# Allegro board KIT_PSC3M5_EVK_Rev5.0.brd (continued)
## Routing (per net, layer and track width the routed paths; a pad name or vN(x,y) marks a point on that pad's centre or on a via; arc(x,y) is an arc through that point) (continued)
VCC_FLASH: length 3.6
  TOP w0.508: U3.8 74.63,25.35 v1(74.55,25.27)
  BOTTOM w0.508: v1(74.55,25.27) 74.42,25.4 C66.2 73.19,25.4 73.17,25.42 R107.1
VCC_IN: length 24.8
  BOTTOM w0.381: TP9.1 107.28,23.65 ; TP9.1 106.2,22.57 ; TP9.1 105.12,23.65 ; 106.39,18.92 D4.K ; D4.K 106.39,21.46 ; D4.K 107.3,20.19 ; D4.K 105.47,20.19 ; U8.12 94.88,21.58 ; C82.1 98.17,22.65 ; C82.1 99.11,21.85 ; C82.1 97.23,21.85 ; C81.1 101.27,21.85 ; C81.1 99.39,21.85 ; C81.1 100.33,22.65 ; C84.1 96.27,21.68 ; C84.1 95.74,21.18 ; C84.1 96.79,21.18 ; 95.54,17.36 R124.1 94.87,16.94 ; 95.77,18.37 R121.2 96.27,17.78 ; C80.1 103.43,21.85 ; C80.1 101.55,21.85 ; C80.1 102.49,22.65 ; 106.39,14.86 D5.K ; D5.K 106.39,17.4 ; D5.K 107.3,16.13 ; D5.K 105.47,16.13 ; U8.13 94.93,21.35
VCC_IO_CAN: length 3.5
  TOP w0.292: U4.5 34.7,14.73
  TOP w0.381: v1(33.75,15.72) C40.2 34.44,14.99 34.7,14.73
  BOTTOM w0.381: R131.1 33.81,16.65 33.81,15.77 v1(33.75,15.72)
VCCD: length 2.3
  TOP w0.292: 69.34,41.15 69.27,41.08 U1.10
  TOP w0.381: 69.34,41.15 C11.1
VDD_POT: length 9.6
  BOTTOM w0.381: R49.2 113.86,55.6 ; R49.2 113.2,54.88 ; R49.2 113.2,56.32 ; 113.82,58.06 J9.2 ; J9.2 113.82,60 ; J9.2 112.85,59.03 ; J9.2 114.79,59.03 ; R1.3 126.6,63.74 ; R1.3 124.8,63.74 ; R1.3 125.7,64.64 ; R1.3 125.7,62.84
VDDA: length 19.9
  TOP w0.292: U1.66 59.14,33.05
  TOP w0.381: 59.14,33.05 59.14,32.02 C30.1 59.72,31.49 59.72,32.28 v1(59.84,32.41)
  L04_SIG2 w0.635: v1(54.76,28.22) v1(54.05,28.22)
  L05_PWR w0.381: 110.31,59.03 J9.1 ; J9.1 111.28,60 ; J9.1 111.28,58.06 ; J9.1 112.25,59.03
  BOTTOM w0.381: 111.28,58.06 J9.1 ; J9.1 111.28,60 ; J9.1 110.31,59.03 ; 111.7,54.88 R49.1 ; R49.1 111.03,55.6 ; R49.1 111.7,56.32 ; 54.51,28.71 R93.1 53.79,29.37
  BOTTOM w0.508: R80.1 60.11,32.68 v1(59.84,32.41) 59.33,31.9 C63.1 FB2.2
  vias: v1(42.57,41.68) v1(42.57,41.05) v1(42.57,40.41) v1(42.57,39.78) v1(42.57,39.14) v1(43.46,41.3) v1(43.46,40.54) v1(43.46,39.78)
VDDD: length 8.1
  TOP w0.292: 69.37,40.54 69.33,40.58 U1.9
  TOP w0.381: 69.37,40.54 69.75,40.16 70,40.16 70.79,39.37 C18.1 v1(70.89,40.16)
  BOTTOM w0.381: R44.1 42.55,56.64 v1(42.32,56.41) ; v1(32.41,26.82) 32.28,26.7 R109.1
  BOTTOM w0.508: v1(70.89,40.16) 71.07,39.98 C54.1 72.66,39.27 FB1.2
VDDIO_0: length 16.4
  TOP w0.292: v1(69.37,46.38) 69.06,46.08 U1.20 ; 53.49,42.08 U1.49 ; U1.40 56.64,48.88 56.35,49.17
  TOP w0.381: v1(54.89,50.08) 54.93,50.12 C2.1 55.68,49.43 55.93,49.17 56.35,49.17 ; v1(51.08,41.94) 51.28,42.14 C9.1 53.11,42.14 53.17,42.08 53.49,42.08
  BOTTOM w0.381: C51.1 50.28,41.53 50.69,41.94 v1(51.08,41.94) ; 70.13,46.16 C46.1 ; C46.1 70.66,46.66 ; C46.1 69.6,46.66 ; 54,49.41 C44.1 v1(54.89,50.08) ; 73.05,45.85 R55.1 ; 70.81,46.52 C45.1 71.53,45.85
  BOTTOM w0.508: R55.1 C45.1
VDDIO_1: length 7.5
  TOP w0.292: U1.80 66.14,33.76 67.31,32.59 68.2,32.59 C27.1 68.25,32.92 67.87,33.3 v1(67.84,33.3)
  BOTTOM w0.381: R78.1 C59.1 68.3,32.54 67.84,32.99 v1(67.84,33.3)
VIN: length 16.2
  TOP w0.381: 98.77,14.6 R42.1 ; R42.1 99.46,15.52 ; R42.1 98.77,16.44
  BOTTOM w0.381: D5.A 111.7,16.13 ; D5.A 110.78,14.86 ; D5.A 109.87,16.13 ; 112.52,15.67 R132.1 ; R132.1 113.02,16.09 ; R132.1 112.03,16.09 ; 116.04,5.88 J20.1 ; J20.1 116.04,8.85 ; J20.1 114.92,7.37 ; J20.1 117.16,7.37 ; 113.68,12.62 C92.1 ; C92.1 113.68,14.05 ; C92.1 113.01,13.34 ; D6.1 113.71,11.92 ; D6.1 113.09,11.3 ; D6.1 113.71,10.68
  vias: v1(99.09,14.38) v1(99.97,15.14) v1(99.97,14.38)
VIN_EXP: length 127.5
  TOP w0.381: 96.17,15.52 R42.2 ; R42.2 96.87,16.44 ; R42.2 96.87,14.6 ; 59.93,5.08 J24.2 ; J24.2 60.96,6.11 ; J24.2 60.96,4.05 ; J24.2 61.99,5.08 ; J1.1 86.87,11.87 ; J1.1 86.87,9.72 ; J1.1 85.79,10.79 ; J1.1 87.95,10.79
  L04_SIG2 w0.889: J24.2 58.93,7.11 32.56,7.11 28.85,10.82 28.85,54.89 31.8,57.84 40.84,57.84 51.23,68.22 60.05,68.22 J5.39
AN_A0: length 8.8
  TOP w0.178: U1.53 53.21,40.08 53.06,39.93 50.46,39.93 C14.2 50.28,40.52 v1(50.16,40.64)
  BOTTOM w0.178: R68.1 49.81,40.28 v1(50.16,40.64)
AN_A1: length 9.3
  TOP w0.178: v1(50.27,38.73) 50.28,38.72 C19.2 50.93,37.85 52.66,39.58 U1.54
  BOTTOM w0.178: R70.1 50.24,38.76 v1(50.27,38.73)
AN_A2: length 10.6
  TOP w0.178: v1(50.27,36.83) 50.28,36.82 C22.2 50.8,35.94 51.05,36.2 51.05,37.24 52.89,39.08 U1.55
  BOTTOM w0.178: v1(50.27,36.83) 49.86,37.24 R71.1
AN_A3: length 12.1
  TOP w0.178: v1(50.27,34.92) 50.28,34.91 C24.2 50.88,34.04 51.44,34.59 51.44,36.93 53.08,38.58 U1.56
  BOTTOM w0.178: v1(50.27,34.92) 47.79,34.92 R74.1
AN_A4: length 13.6
  TOP w0.178: v1(50.27,33.02) 50.28,33.01 C26.2 50.93,32.13 51.21,32.41 51.21,33.63 51.84,34.26 51.84,36.65 53.26,38.08 U1.57
  BOTTOM w0.178: R77.1 47.79,33.4 49.89,33.4 v1(50.27,33.02)
AN_A5: length 15.1
  TOP w0.178: v1(50.27,31.11) 50.28,31.1 C29.2 50.95,30.23 51.66,30.94 51.66,33.38 52.25,33.96 52.25,36.4 53.43,37.58 U1.58
  BOTTOM w0.178: v1(50.27,31.11) 48.72,32.66 R82.1
AN_A6: length 16.6
  TOP w0.178: U1.59 53.56,37.08 52.63,36.14 52.63,33.71 52.15,33.22 52.15,29.51 50.98,28.35 50.31,28.35 C38.2 50.28,29.2 v1(50.27,29.21)
  BOTTOM w0.178: v1(50.27,29.21) 48.34,31.14 R85.1
AN_A7: length 18.1
  TOP w0.178: U1.60 53.72,36.58 53.09,35.94 53.09,33.5 52.63,33.05 52.63,29.18 51.38,27.94 51.38,26.85 50.95,26.42 C39.2 50.28,27.29 v1(50.27,27.3)
  BOTTOM w0.178: v1(50.27,27.3) 47.96,29.62 R97.1
AN_B2: length 8.9
  TOP w0.178: U1.63 57.64,33.51 56.9,32.77 55.3,32.77 v1(55.07,32.54) 54.36,31.83 C31.2
  BOTTOM w0.178: R94.1 52.73,31.47 53.16,31.9 54.38,31.9 55.02,32.54 v1(55.07,32.54)
AN_B3: length 6.8
  TOP w0.178: U1.64 58.14,33.07 v1(57.68,32.61) 57.51,32.44 56.16,32.44 55.88,32.16 C32.2
  BOTTOM w0.178: v1(57.68,32.61) 57.81,32.49 R91.1
AN_B4: length 6.9
  TOP w0.178: U1.67 59.64,33.4 v1(60.68,32.36) 60.68,31.96 C33.2
  BOTTOM w0.178: R90.1 62.89,31.45 62.53,31.8 61.24,31.8 v1(60.68,32.36)
AN_B5: length 8
  TOP w0.178: C34.2 63.02,32.41 v1(62.76,32.66) 61.24,32.66 60.14,33.76 U1.68
  BOTTOM w0.178: v1(62.76,32.66) 63.01,32.66 R89.1
AN_B6: length 9.5
  TOP w0.178: U1.69 60.64,33.81 61.28,33.17 63.14,33.17 63.86,32.46 v1(64.47,32.46) 64.54,32.46 64.92,32.08 C35.2
  BOTTOM w0.178: R88.1 66.62,31.47 66.19,31.9 65.02,31.9 v1(64.47,32.46)
AN_B7: length 11.1
  TOP w0.178: U1.70 61.14,33.78 61.37,33.55 63.27,33.55 63.88,32.94 65.71,32.94 v1(65.89,32.77) 65.96,32.77 66.7,32.03 C36.2
  BOTTOM w0.178: R87.1 68.25,31.39 66.88,32.77 v1(65.89,32.77)
ARD_A0: length 74.8
  TOP w0.178: J24.23 87.66,3.78 87.66,6.38 88.8,7.52 90.2,7.52 91.95,9.27 J2.1
  L03_SIG1 w0.157: v1(45.63,41.3) 46.65,40.28 49.56,40.28 56.34,33.5 64.08,33.5 65.38,32.21 66.9,32.21 68.22,30.89 69.62,30.89 71.48,29.03 74.02,29.03 77.34,25.7 82.14,25.7 87.15,20.7 87.83,20.7 91.21,17.32 91.21,11.53 J2.1
  BOTTOM w0.178: v1(45.63,41.3) 45.63,40.41 R68.2
ARD_A1: length 78
  TOP w0.178: J2.2 94.49,9.19 92.74,7.44 92.74,4.09 91.44,2.79 J24.25
  L03_SIG1 w0.157: J2.2 93.22,9.53 91.62,9.53 90.83,10.31 90.83,16.15 88.57,18.41 88.57,19.15 87.5,20.22 86.92,20.22 81.81,25.32 76.25,25.32 73.89,27.69 72.16,27.69 69.34,30.51 68.02,30.51 66.65,31.88 64.39,31.88 63.12,33.15 56.67,33.15 55.58,32.05 53.16,32.05 50.88,34.34 48.56,34.34 47.02,35.89 47.02,36.35 v1(44.6,38.76)
  BOTTOM w0.178: R70.2 v1(44.6,38.76)
ARD_A2: length 79.8
  TOP w0.178: J2.3 97.03,9.4 95.28,7.65 95.28,3.84 J24.27
  L03_SIG1 w0.157: v1(44.6,37.24) 46.15,35.69 46.15,35.36 49.78,31.72 55.8,31.72 56.54,32.46 57.05,32.46 57.96,31.55 66.42,31.55 67.92,30.05 69.19,30.05 72.01,27.23 73.86,27.23 76.76,24.33 82.12,24.33 86.74,19.71 87.43,19.71 88.11,19.02 88.11,18.08 90.45,15.75 90.45,10.06 91.34,9.17 95.4,9.17 J2.3
  BOTTOM w0.178: R71.2 v1(44.6,37.24)
ARD_A3: length 92.1
  TOP w0.178: J24.22 86.36,6.35 88.42,8.41 89.69,8.41 90.53,9.25 90.53,11.66 91.26,12.4 97.51,12.4 99.11,10.79 J2.4
  L03_SIG1 w0.157: v1(44.6,35.71) 47.07,33.25 47.07,32.03 47.9,31.19 48.62,31.19 49.2,30.61 50.57,30.61 51.36,31.39 55.85,31.39 56.03,31.22 66.22,31.22 67.79,29.64 68.96,29.64 71.78,26.82 73.79,26.82 76.61,24 81.91,24 86.64,19.28 87.05,19.28 87.63,18.69 87.63,18.01 90.07,15.57 90.07,9.8 91.16,8.71 96.09,8.71 96.88,9.5 98.27,9.5 J2.4
  BOTTOM w0.178: R74.2 v1(44.6,35.71)
ARD_A4: length 208.5
  L03_SIG1 w0.157: 46.05,32.36 46.15,32.26 ; 46.05,32.36 15.98,32.36 J16.1 ; 46.05,32.36 46.15,32.46 ; 46.15,32.26 46.15,31.88 47.29,30.73 48.26,30.73 48.74,30.25 50.85,30.25 51.66,31.06 55.68,31.06 55.85,30.89 65.94,30.89 67.59,29.24 68.81,29.24 74.37,23.67 81.71,23.67 86.39,19 86.39,17.81 89.69,14.5 89.69,9.55 90.86,8.38 99.69,8.38 J2.5 ; 46.15,32.26 46.15,32.46 ; 46.15,32.46 46.15,32.72 v1(44.65,34.21) 41.91,36.96 41.91,46.28 38.25,49.94 12.73,49.94 9.55,53.11 9.55,55.3 9.19,55.65 7.01,55.65 J8.2
  L03_SIG1 w0.178: J16.1 6.99,6.35 J21.2
  L04_SIG2 w0.157: J2.5 102.11,9.53 99.85,7.26 90.45,7.26 88.9,5.71 J24.24
  BOTTOM w0.157: R77.2 44.68,34.19 v1(44.65,34.21)
ARD_A5: length 215
  L03_SIG1 w0.157: 8.26,54.36 8.26,53.14 12.09,49.3 38.25,49.3 41.45,46.1 41.45,36.55 44.5,33.5 v1(44.5,32.84) 14.17,32.84 5.74,24.41 5.74,17.4 4.47,16.13 4.47,4.47 5.11,3.84 7.01,3.84 8.26,5.08 ; v1(44.89,28.68) 45.08,28.88 48.92,28.88 49.07,28.73 51.1,28.73 51.92,29.54 57.66,29.54 57.96,29.84 61.37,29.84 61.62,29.59 66.04,29.59 67.16,28.47 68.22,28.47 73.94,22.76 76.86,22.76 82.83,16.79 86.13,16.79 88.93,14 88.93,9.04 90.4,7.57 102.57,7.57 104.65,9.65 J2.6
  L04_SIG2 w0.157: J2.6 100.74,6.88 93.37,6.88 91.57,5.08 J24.26
  BOTTOM w0.157: R82.2 44.68,32.66 v1(44.5,32.84) 44.09,32.44 44.09,29.44 44.85,28.68 v1(44.89,28.68)
ARD_A6: length 89.5
  L03_SIG1 w0.157: v1(44.6,31.14) 46.02,29.72 51.56,29.72 51.71,29.87 57.53,29.87 57.86,30.2 61.57,30.2 61.85,29.92 66.34,29.92 67.4,28.85 68.43,28.85 73.94,23.34 81.43,23.34 83.69,21.08 83.69,17.93 84.35,17.27 86.16,17.27 89.31,14.12 89.31,9.3 90.63,7.98 101.45,7.98 103.4,9.93 103.4,11.58 104.04,12.22 105.77,12.22 J2.7 103.15,6.76 103.15,6.63 J24.34
  BOTTOM w0.178: R85.2 v1(44.6,31.14)
ARD_A7: length 58.1
  L03_SIG1 w0.157: v1(44.58,29.62) 44.58,29.46 44.42,29.31 44.42,28.49 45.05,27.86 48.56,27.86 49.05,28.35 51.28,28.35 52.15,29.21 57.78,29.21 58.06,29.49 61.19,29.49 61.42,29.26 63.27,29.26 63.93,28.6 63.93,27.58 64.69,26.82 67.06,26.82 72.59,21.29 76.12,21.29 81.58,15.82 81.58,14.88 82.98,13.49 82.98,8.64 83.82,7.8 J24.20
  BOTTOM w0.178: R97.2 v1(44.58,29.62)
ARD_B0: length 24.4
  TOP w0.178: R36.1 40.67,35.97 v1(43.48,38.79) ; v1(53.24,32.66) 54,33.43 56.08,33.43 56.64,33.99 U1.61
  L03_SIG1 w0.157: v1(43.48,38.79) 44.09,39.4 45.62,39.4 48.84,36.17 50.57,36.17 53.24,33.5 v1(53.24,32.66)
ARD_B0_EXP: length 70.3
  TOP w0.178: R33.1 v1(39.14,37.47)
  BOTTOM w0.178: v1(39.14,37.47) 39.14,25.3 38.25,24.41 38.25,11.81 40.49,9.58 53.85,9.58 56.87,6.55 77.27,6.55 J24.16
ARD_B1: length 33.7
  TOP w0.178: v1(38.51,51.21) 38.49,51.22 R7.2 ; v1(54,32.66) 54.43,33.1 56.59,33.1 57.14,33.65 U1.62
  L03_SIG1 w0.157: v1(38.51,51.21) 42.67,47.04 42.67,43.23 46.89,39.01 49.25,39.01 54,34.26 v1(54,32.66)
ARD_B1_EXP: length 88.3
  TOP w0.178: v1(40.41,52.73) 39.99,53.15 R7.1
  BOTTOM w0.178: v1(40.41,52.73) 40.23,52.55 40.23,39.78 39.65,39.19 39.65,25.04 38.68,24.08 38.68,12.09 40.74,10.03 54.1,10.03 57.12,7.01 79.35,7.01 J24.18
ARD_B2: length 47.7
  L03_SIG1 w0.157: v1(52.88,28.12) 53.87,27.13 59.97,27.13 61.32,25.78 66.98,25.78 67.72,25.04 67.72,24.13 72.26,19.58 75.87,19.58 78.05,17.4 78.05,9.12 80.04,7.14 80.04,3.78 J24.17
  BOTTOM w0.178: v1(52.88,28.12) 52.73,28.27 R94.2
ARD_B3: length 44.3
  L03_SIG1 w0.157: v1(57.56,28.35) 58.37,27.53 63.27,27.53 64.54,26.26 67.01,26.26 72.36,20.9 76.02,20.9 80.16,16.76 80.16,12.73 80.54,12.34 80.54,8.79 82.58,6.76 82.58,3.78 J24.19
  BOTTOM w0.178: v1(57.56,28.35) 57.56,29.12 R91.2
ARD_B5: length 41.5
  L03_SIG1 w0.157: v1(64.8,28.09) 65.33,27.56 67.06,27.56 72.97,21.64 76.4,21.64 85.62,12.42 85.62,9.8 89.05,6.38 92.68,6.38 J24.28
  BOTTOM w0.178: R89.2 v1(64.8,28.09)
ARD_B6: length 42.6
  L03_SIG1 w0.157: J24.30 94.84,6.76 89.81,6.76 88.16,8.41 88.16,11.58 87.4,12.34 86.21,12.34 76.53,22.02 73.28,22.02 67.21,28.09 v1(66.62,28.09)
  BOTTOM w0.178: R88.2 v1(66.62,28.09)
ARD_B7: length 56.7
  TOP w0.178: J24.32 101.6,7.62 106.55,7.62 J2.8
  L03_SIG1 w0.157: v1(68.25,27.71) 73.56,22.4 76.68,22.4 86.23,12.85 87.53,12.85 88.54,11.84 88.54,8.79 90.22,7.11 97.03,7.11 J24.32
  BOTTOM w0.178: R87.2 v1(68.25,27.71)
CAN_RX1: length 49.6
  TOP w0.178: v1(41.92,16.41) 41.92,23.64 45.36,27.08 45.36,40.03 44.65,40.74 44.65,46.08 45.54,46.96 v1(46.41,46.96) ; v1(57.43,46.25) 58.14,46.97 U1.37
  L03_SIG1 w0.157: v1(46.41,46.96) 50.06,46.96 51.51,48.41 54.25,48.41 55.4,47.27 57.18,47.27 57.43,47.02 v1(57.43,46.25)
  BOTTOM w0.178: R137.2 v1(41.92,16.41)
CAN_STB: length 1.6
  TOP w0.178: U4.8 v1(35.46,12.1)
  BOTTOM w0.178: v1(35.46,12.1) 35.46,12.09 R151.2
CAN_TX1: length 49.7
  TOP w0.178: v1(42.06,13.36) 42.7,14 42.7,23.14 45.87,26.31 45.87,40.28 45.14,41.02 45.14,44.63 v1(46.89,46.38) ; U1.38 57.64,47.1 57.3,46.76 v1(56.92,46.76)
  L03_SIG1 w0.157: v1(56.92,46.76) 55.4,46.76 54.13,48.03 51.89,48.03 50.24,46.38 v1(46.89,46.38)
  BOTTOM w0.178: v1(42.06,13.36) 41.92,13.22 R148.1
CS: length 35.2
  TOP w0.15: v1(85.42,27.23) 85.4,27.2 85.4,26.43 R41.2
  TOP w0.178: v1(62,36.86) 61.64,36.5 U1.71
  L03_SIG1 w0.157: v1(85.42,27.23) 84.56,26.37 77.67,26.37 73.91,30.12 72.01,30.12 67.82,34.32 61.7,34.32 61.04,34.98 61.04,36.55 61.34,36.86 v1(62,36.86)
  BOTTOM w0.15: R20.2 85.4,27.2 v1(85.42,27.23)
DFU_SW1: length 94.1
  TOP w0.178: v1(70.26,8.41) 71.12,7.54 J24.10 ; v1(66.83,46.79) 66.55,46.79 66.14,47.19 U1.21
  L04_SIG2 w0.157: v1(66.83,46.79) 67.31,46.79 68.86,45.24 68.86,39.4 69.42,38.84 70.43,38.84 71.67,37.61 71.67,36.59 76.5,31.75 87.78,31.75 88.7,30.84 88.7,26.24 85.39,22.94 83.24,22.94 76.1,15.8 76.1,14.55 72.92,11.38 72.92,6.88 J24.10
  BOTTOM w0.178: v1(70.26,8.41) 58.06,8.41 54.51,11.96 52.91,11.96 J19.2
DFU_SW2: length 71.6
  TOP w0.178: U1.22 65.64,46.34 65.3,46 65.3,42.7 v1(65.05,42.44)
  L03_SIG1 w0.178: J22.2 52.15,2.95 58.57,2.95 59.46,3.84 69.82,3.84 J24.9
  L04_SIG2 w0.157: J24.9 69.93,3.73 69.93,6.7 67.84,8.79 67.84,12.09 68.86,13.11 68.86,15.52 69.57,16.23 69.57,24.54 68.78,25.32 68.78,33.12 67.34,34.57 67.34,37.24 65.05,39.52 v1(65.05,42.44)
ECO_IN: length 5.7
  TOP w0.178: U1.14 69.11,43.08 70.38,44.35 72.11,44.35 72.42,44.65 72.42,45.35 R18.2
ECO_OUT: length 7.1
  TOP w0.178: U1.15 68.98,43.58 69.37,43.97 69.37,45.49 70.13,46.25 72.24,46.25 72.42,46.43 R13.2
ETM_TRACE_CLK: length 51.3
  TOP w0.15: J14.12 105.03,44.96 104.3,45.69 v1(99.7,45.69)
  TOP w0.157: v1(64.24,52.3) 64.26,52.32 71.27,52.32 72.16,51.44 79.38,51.44 80.11,50.7 v1(90.07,50.7)
  L03_SIG1 w0.157: v1(90.07,50.7) 91.9,50.7 92.06,50.54 92.06,49.92 92.21,49.76 92.53,49.76 92.69,49.92 92.69,50.54 92.84,50.7 94.68,50.7 v1(99.7,45.69)
  BOTTOM w0.157: R24.1 61.33,52.06 61.9,52.63 63.91,52.63 v1(64.24,52.3)
ETM_TRACE_D0: length 51.6
  TOP w0.15: J14.14 99.19,46.23 97.51,44.55 97.51,38.29 96.88,37.65 96.88,34.49 95.83,33.45 95.83,30.68 97.3,29.22 97.3,27.75 97,27.46 90.19,27.46 90.04,27.31 90.04,25.22 89.89,25.07 89.59,25.07 89.44,25.22 89.44,27.31 89.29,27.46 88.99,27.46 88.84,27.31 88.84,25.22 88.69,25.07 88.39,25.07 88.24,25.22 88.24,27.31 88.09,27.46 87.73,27.46 87.58,27.31 87.58,25.04 87.35,24.81 v1(86.43,24.81)
  BOTTOM w0.15: R20.1 v1(86.43,24.81)
ETM_TRACE_D1: length 51.7
  TOP w0.15: J14.16 99.87,47.5 97.16,44.78 97.16,38.38 96.55,37.77 96.55,34.72 95.43,33.6 95.43,30.51 96.8,29.13 96.8,28.09 96.49,27.79 86.16,27.79 83.39,30.56 81,30.56 80.65,30.2 80.65,28.35 80.44,28.14 v1(79.07,28.14)
  BOTTOM w0.15: R16.1 78.26,28.12 78.29,28.14 v1(79.07,28.14)
ETM_TRACE_D2: length 51.8
  TOP w0.15: v1(86.36,28.32) 85.95,28.73 85.95,29.31 86.16,29.51 86.89,29.51 87.12,29.29 87.12,28.4 87.38,28.14 87.64,28.14 87.79,28.29 87.79,28.93 87.94,29.08 88.24,29.08 88.39,28.93 88.39,28.29 88.54,28.14 88.84,28.14 88.99,28.29 88.99,28.93 89.14,29.08 89.44,29.08 89.59,28.93 89.59,28.29 89.74,28.14 93.25,28.14 93.4,28.29 93.4,29.47 93.55,29.62 93.85,29.62 94,29.47 94,28.29 94.15,28.14 94.45,28.14 94.6,28.29 94.6,29.47 94.75,29.62 95.05,29.62 95.2,29.47 95.2,28.29 95.35,28.14 96.04,28.14 96.27,28.37 96.27,29.08 95.02,30.33 95.02,33.73 96.22,34.93 96.22,37.9 96.8,38.48 96.8,45.01 100.56,48.77 J14.18
  BOTTOM w0.15: v1(86.36,28.32) 86.36,28.27 86.21,28.12 R12.1
ETM_TRACE_D3: length 51.8
  TOP w0.15: J14.20 101.24,50.04 96.37,45.16 96.37,38.53 95.89,38.05 95.89,35.15 94.59,33.86 94.59,31.24 92.08,28.73 90.6,28.73 89.26,30.07 84.53,30.07 83.62,30.99 80.52,30.99 78.19,28.66 78.19,25.13 v1(78.51,24.81)
  BOTTOM w0.15: R10.1 v1(78.51,24.81)
EXT_CLK: length 6.3
  TOP w0.178: R27.2 75.12,39.04 76.99,37.17 TP4.1
HDR_3V3: length 39.6
  L03_SIG1 w0.381: 76.71,11.87 J1.5 75.63,10.79
  L04_SIG2 w0.381: J21.7 19.48,5.08 ; J21.7 18.41,6.15 ; J21.7 18.41,4.01 ; 22.23,22.29 J16.7 ; J16.7 23.3,23.37 ; J16.7 22.23,24.45
  L05_PWR w0.381: J1.5 76.71,11.87 ; J1.5 75.63,10.79 ; J1.5 76.71,9.72 ; J1.5 77.79,10.79 ; J24.39 109.22,3.57 ; J24.39 110.25,2.54 ; J24.39 109.22,1.51 ; J24.39 108.19,2.54 ; J8.7 19.48,54.36 ; J8.7 18.41,53.29 ; J8.7 17.35,54.36 ; J8.7 18.41,55.42 ; J5.2 109.22,65.8 ; J5.2 110.25,64.77 ; J5.2 108.19,64.77 ; J5.2 109.22,63.74 ; J21.7 18.41,6.15 ; J21.7 19.48,5.08 ; J21.7 18.41,4.01 ; J21.7 17.35,5.08
  BOTTOM w0.292: Q7.4 69.87,15.9 69.75,15.77 v1(69.75,15.27)
  BOTTOM w0.381: J1.5 76.71,11.87 ; J1.5 77.79,10.79 ; J1.5 75.63,10.79 ; J1.5 76.71,9.72 ; R141.2 76.48,13.79 ; R141.2 75.81,14.51 ; R141.2 75.81,13.07 ; 75.93,14.89 Q5.S ; Q5.S 75.93,16.13 ; Q5.S 76.6,15.51 ; 70.35,15.49 Q7.4
  vias: v1(70.13,14.76)
HDR_5V0: length 24.3
  TOP w0.381: J1.4 80.33,10.79 ; J1.4 79.25,11.87 ; J1.4 78.17,10.79 ; J1.4 79.25,9.72
  L03_SIG1 w0.381: 22.23,45.15 J12.7 ; J12.7 23.3,46.23 ; J12.7 21.15,46.23 ; J12.7 22.23,47.31 ; J21.1 3.17,6.15 ; J21.1 3.17,4.01 ; J21.1 2.11,5.08 ; J8.1 4.24,54.36 ; J8.1 3.17,53.29 ; J8.1 2.11,54.36 ; J8.1 3.17,55.42
  BOTTOM w0.292: v1(79.38,16.28) 79.4,16.28 79.5,16.38 Q6.4
  BOTTOM w0.381: 85.68,15.42 Q4.S 86.35,16.04 ; J1.4 79.25,11.87 ; J1.4 79.25,9.72 ; J1.4 80.33,10.79 ; 85.53,13.23 R143.2 ; R143.2 86.23,14.15 ; R143.2 85.53,15.07 ; 80.02,15.97 Q6.4
  vias: v1(73.69,8.92) v1(74.32,9.17) v1(74.32,8.53) v1(75.08,9.17) v1(75.08,8.53) v1(79.65,15.65) v1(86.64,14.76) v1(86.64,14.12) v1(86.64,13.49)
HDR_I2C_SCL: length 164.1
  TOP w0.178: J3.10 56.82,59.05 54.64,56.87 v1(54.64,56.29)
  L03_SIG1 w0.157: v1(87.16,52.1) 87.16,52.74 86.23,53.67 81.97,53.67 81.32,54.31 81.32,54.79 84.96,58.43 84.96,61.26 v1(84.48,61.75) ; v1(54.64,56.29) 53.95,55.6 41.93,55.6 41.5,56.03 28.68,56.03 28.17,56.54 15.52,56.54 J8.5
  L04_SIG2 w0.157: J12.5 17.14,49.12 13.34,52.93 J8.5 ; J5.21 82.65,68.48 80.42,68.48 79.89,67.95 79.89,64.01 77.88,62 62.89,62 J3.10
  L04_SIG2 w0.178: J5.21 84.99,66.14 84.99,62.26 v1(84.48,61.75)
  BOTTOM w0.178: R47.2 v1(87.16,52.1) ; J12.5 17.14,34.7 10.82,28.37 10.82,19.76 9.58,18.52 9.58,4.04 10.08,3.53 11.79,3.53 J21.5
HDR_I2C_SDA: length 162.5
  TOP w0.178: v1(55.56,56.32) 55.88,56.01 60.68,56.01 62.48,57.81 J3.9
  L03_SIG1 w0.157: v1(83.46,61.75) 84.35,60.86 84.35,58.45 80.98,55.07 80.98,54.18 81.9,53.25 84.2,53.25 v1(85.36,52.1) ; v1(55.56,56.32) 54.97,56.92 41.81,56.92 41.55,56.67 29.18,56.67 28.8,57.05 13.49,57.05 J8.4
  L04_SIG2 w0.157: J3.9 65.05,61.62 78.26,61.62 80.2,63.56 80.2,66.23 J5.23
  L04_SIG2 w0.178: J12.6 19.68,48.31 14.63,53.37 14.63,55.14 14,55.78 12.22,55.78 J8.4 ; v1(83.46,61.75) 82.58,62.64 82.58,66.19 81.46,67.31 J5.23
  BOTTOM w0.178: J21.4 12.09,6.38 12.09,18.54 13.36,19.81 13.36,28.93 19.68,35.26 J12.6 ; v1(85.36,52.1) R48.2
I2C_SCL: length 39.4
  TOP w0.178: U1.79 65.64,35.54 v1(66.19,36.09)
  BOTTOM w0.178: R53.2 88.81,48.41 88.87,48.47 R50.1 88.87,49.61 88.66,49.82 R47.1 88.66,51.78 87.43,53.01 84.76,53.01 81.46,49.71 81.46,46.38 78.82,43.74 74.7,43.74 72.77,41.81 69.24,41.81 68.12,40.69 68.12,39.22 66.19,37.29 v1(66.19,36.09)
I2C_SDA: length 29.5
  TOP w0.178: U1.2 v1(66.81,37.08)
  BOTTOM w0.178: v1(66.81,37.08) 68.73,39 68.73,40.41 69.57,41.25 73.03,41.25 74.96,43.18 79.07,43.18 82.02,46.13 82.02,49.42 83.04,50.44 R48.1 83.86,49.69 83.7,49.54 R51.1 83.7,48.47 83.76,48.41 R54.2
KP_I2C_SCL: length 7.8
  TOP w0.178: U2.38 v1(90.29,43.55)
  BOTTOM w0.178: v1(90.29,43.55) 90.29,45.78 89.18,46.89 87.58,46.89 87.4,47.07 87.4,47.59 R53.1
KP_I2C_SDA: length 9.4
  TOP w0.178: v1(89.81,42.95) 89.89,42.88 U2.39
  BOTTOM w0.178: R54.1 85.26,46.75 85.62,46.38 87.76,46.38 87.84,46.47 88.23,46.47 88.5,46.19 88.5,45.71 88.96,45.25 89.35,45.25 89.81,44.79 v1(89.81,42.95)
KP_RESET: length 29.7
  TOP w0.157: U2.3 v1(85.89,33.28)
  TOP w0.178: R25.2 v1(101.36,44.58)
  L03_SIG1 w0.157: v1(101.36,44.58) 101.36,36.94 100.25,35.84 99.7,35.84 98.63,36.91 95.91,36.91 95,35.99 95,33.86 93.61,32.47 92.24,32.47 91.03,33.68 86.28,33.68 v1(85.89,33.28)
KP_SWCLK: length 17.5
  TOP w0.157: U2.47 86.69,42.02 v1(86.69,43.26)
  TOP w0.178: v1(97.49,37.49) 97.61,37.36 R37.1
  L03_SIG1 w0.157: v1(86.69,43.26) 86.79,43.36 87.43,43.36 88.34,42.44 91.97,42.44 92.23,42.19 95.1,42.19 v1(95.12,42.21)
  BOTTOM w0.178: v1(97.49,37.49) 97.49,40.74 96.01,42.21 v1(95.12,42.21)
KP_SWDIO: length 17.7
  TOP w0.157: v1(87.2,42.8) 87.09,42.69 U2.46
  TOP w0.178: R39.1 98.46,36.31 v1(98.44,36.33)
  L03_SIG1 w0.157: v1(95.68,41.63) 95.66,41.61 92.02,41.61 91.74,41.88 88.11,41.88 v1(87.2,42.8)
  BOTTOM w0.178: v1(98.44,36.33) 97.92,36.86 97.23,36.86 96.93,37.16 96.93,40.39 v1(95.68,41.63)
KP_USB_DM: length 41.9
  TOP w0.114: J15.B7 123.43,29.1 123.57,29.23 123.92,29.23 v1(124.21,28.94) ; J15.A7 122,30.1 121.86,30.23 121.6,30.23 v1(121.31,29.94)
  L03_SIG1 w0.114: v1(97.34,36.12) 97.06,35.84 96.64,35.84 96.38,35.58 96.38,34.78 98.55,32.61 116.54,32.61 118.93,30.22 121.03,30.22 v1(121.31,29.94) 121.59,30.22 121.95,30.22 122.95,29.22 123.93,29.22 v1(124.21,28.94)
  BOTTOM w0.114: U7.1 119.33,30.37 119.9,30.37 120.85,29.41 121.7,29.41 121.95,29.66 121.95,30.12 121.83,30.23 121.6,30.23 v1(121.31,29.94) ; v1(97.34,36.12) 97.05,35.83 96.58,35.83 R72.1
KP_USB_DP: length 41.8
  TOP w0.114: v1(121.31,30.75) 121.6,30.46 121.87,30.46 122.01,30.6 J15.B6 ; v1(124.21,29.75) 123.92,29.46 123.57,29.46 123.43,29.6 J15.A6
  L03_SIG1 w0.114: v1(124.21,29.75) 123.93,29.47 123.06,29.47 122.06,30.47 121.59,30.47 v1(121.31,30.75) 121.03,30.47 119.03,30.47 116.64,32.86 98.66,32.86 96.63,34.88 96.63,35.47 96.75,35.59 97.06,35.59 v1(97.34,35.31)
  BOTTOM w0.114: R75.1 96.58,35.6 97.05,35.6 v1(97.34,35.31) ; v1(121.31,30.75) 121.6,30.46 121.93,30.46 122.17,30.21 122.17,29.57 121.79,29.18 120.76,29.18 119.81,30.14 119.33,30.14 U7.2
KP_VBUS: length 12.3
  BOTTOM w0.381: 112.57,20.06 R117.1 ; R117.1 113.07,20.48 ; R117.1 112.08,20.48 ; Q3.D 103.02,26.44 ; Q3.D 102.55,25.82 ; Q3.D 103.02,25.2 ; Q3.D 103.49,25.82 ; 105.95,27.2 R102.2 106.64,26.28 ; R108.2 100.56,26.06 ; R108.2 99.61,26.78 ; R108.2 99.61,25.03 ; D4.A 111.7,20.19 ; D4.A 110.78,18.92 ; D4.A 110.78,21.46 ; D4.A 109.87,20.19
KP_VBUS_IN: length 9.3
  TOP w0.381: TP7.1 v1(117.5,27.84)
  BOTTOM w0.381: R102.1 109.24,27.2 ; R102.1 108.54,28.12 ; R102.1 108.54,26.28 ; D3.K 120.1,27.08 ; D3.K 119.48,27.7 ; D3.K 118.86,27.08 ; C65.1 118.35,26.94 ; C65.1 116.91,26.94 ; C65.1 117.63,27.61 ; 109.12,30.25 Q2.D ; Q2.D 110.36,30.25 ; Q2.D 109.74,29.78
  vias: v1(121.06,32.28) v1(121.06,27.46) v1(121.44,27.97) v1(121.69,32.28)
LPCOMP0_INN: length 68.6
  L04_SIG2 w0.157: v1(79.88,29.54) 77.67,29.54 76.38,30.84 74.8,30.84 71.32,34.32 70.13,34.32 68.86,35.59 68.86,37.87 67.72,39.01 67.72,44.04 67.16,44.6 66.73,44.6 66.45,44.88 66.45,45.36 65.56,46.25 65.56,47.65 67.59,49.68 67.59,53.11 72.03,57.56 84.35,57.56 85.62,58.83 85.62,59.72 87.45,61.54 90.53,61.54 92.52,63.54 92.52,65.85 J5.13
  BOTTOM w0.15: R95.1 79.81,29.62 v1(79.88,29.54)
LPCOMP0_INP: length 77.7
  L04_SIG2 w0.157: v1(86.82,27.2) 86.16,26.54 77.19,26.54 75.44,28.3 74.12,28.3 67.72,34.7 67.72,37.36 65.68,39.4 65.68,42.57 64.41,43.84 64.41,48.41 66.32,50.32 66.32,59.79 67.77,61.24 84.73,61.24 87.53,64.03 87.53,66.14 J5.19
  BOTTOM w0.15: R113.1 86.9,27.1 86.82,27.18 v1(86.82,27.2)
LPCOMP1_INN: length 69.7
  L04_SIG2 w0.157: J5.17 88.9,66.85 89.98,65.77 89.98,63.57 89.6,63.19 87.44,63.19 85.12,60.86 69.88,60.86 68.86,59.84 68.86,57.81 66.7,55.65 66.7,50.06 64.8,48.16 64.8,44.09 66.07,42.82 66.07,39.52 68.1,37.49 68.1,35.05 74.35,28.8 75.67,28.8 76.73,27.74 78.51,27.74 v1(78.95,27.3)
  BOTTOM w0.15: R100.1 v1(78.95,27.3)
LPCOMP1_INP: length 76.4
  L04_SIG2 w0.157: J5.15 91.44,66.8 90.36,65.72 90.36,63.31 89.89,62.84 87.6,62.84 85.22,60.46 72.14,60.46 71.4,59.72 71.4,57.94 67.08,53.62 67.08,49.81 65.18,47.9 65.18,44.22 67.21,42.19 67.21,39.01 68.48,37.74 68.48,35.33 70,33.81 70.89,33.81 74.32,30.38 76.12,30.38 77.42,29.08 87.33,29.08 v1(87.86,29.62)
  BOTTOM w0.15: R104.1 v1(87.86,29.62)
MISO: length 34.2
  TOP w0.178: v1(63.02,36.86) 62.64,36.48 U1.73
  L03_SIG1 w0.157: v1(85.24,30.53) 85.24,30.05 84.76,29.57 82.02,29.57 80.09,31.5 73.96,31.5 72.14,33.32 72.14,35.2 71.76,35.59 69.86,35.59 69.7,35.74 69.7,36.49 69.55,36.65 69.23,36.65 69.07,36.49 69.07,35.74 68.92,35.59 68.6,35.59 68.44,35.74 68.44,36.49 68.29,36.65 67.97,36.65 67.81,36.49 67.81,35.74 67.66,35.59 66.04,35.59 64.41,37.21 63.37,37.21 v1(63.02,36.86)
  BOTTOM w0.15: R105.1 85.4,30.38 v1(85.24,30.53)
MOSI: length 34.2
  TOP w0.178: U1.72 v1(62.14,35.84)
  L03_SIG1 w0.157: v1(77.45,30.61) 77.93,31.09 79.24,31.09 79.4,30.93 79.4,29.34 79.3,29.24 78.91,29.24 78.75,29.39 78.75,29.87 78.6,30.02 78.28,30.02 78.12,29.87 78.12,29.43 78,29.31 77.48,29.31 75.77,31.01 73.94,31.01 73.62,31.33 73.4,31.33 72.97,30.91 72.75,30.91 72.53,31.13 72.53,31.35 72.95,31.78 72.95,32 72.73,32.22 72.51,32.22 72.08,31.8 71.86,31.8 71.64,32.02 71.64,32.24 72.06,32.67 72.06,32.89 71.65,33.3 71.4,33.3 71.24,33.46 71.24,34.51 71.09,34.67 70.77,34.67 70.61,34.51 70.61,33.46 70.46,33.3 69.95,33.3 69.26,33.99 69.26,34.22 69.66,34.62 69.66,34.84 69.43,35.06 69.21,35.06 68.81,34.66 68.59,34.66 68.12,35.13 64.59,35.13 63.47,36.25 62.55,36.25 v1(62.14,35.84)
  BOTTOM w0.15: R96.1 v1(77.45,30.61)
P0_1: length 54.9
  TOP w0.178: R21.2 70.26,43.46 v1(69.88,43.08)
  L04_SIG2 w0.157: v1(73.56,52.6) 74.9,53.95 97.26,53.95 100.85,57.54 100.85,61.4 102.9,63.45 102.9,66.07 J5.5
  BOTTOM w0.178: v1(69.88,43.08) 72.31,43.08 74.45,45.21 74.45,51.71 v1(73.56,52.6)
P1_0: length 72
  TOP w0.178: R17.2 v1(70,45.36)
  L04_SIG2 w0.157: v1(97.31,8.92) 91.59,8.92 88.16,12.34 88.16,23.34 90.91,26.09 90.91,31.88 88.32,34.47 80.9,34.47 v1(70,45.36)
  BOTTOM w0.178: J24.37 106.68,2.59 105.44,3.84 105.44,6.12 102.64,8.92 v1(97.31,8.92)
P1_1: length 44.4
  TOP w0.178: R13.1 70.92,48.26 v1(70.64,48.54)
  L04_SIG2 w0.157: v1(70.64,48.54) 70.64,51.98 73.68,55.02 80.42,55.02 81.08,55.68 93.65,55.68 95.66,57.68 95.66,59.33 100.23,63.91 100.23,65.94 J5.7
P2_0: length 42.8
  TOP w0.15: R158.2 99.94,42.41 v1(99.85,42.32) 99.96,42.2 R28.2 R29.2
  TOP w0.178: v1(66.95,45.08) U1.18
  L03_SIG1 w0.157: v1(99.85,42.32) 98.76,42.32 94.11,46.96 83.79,46.96 79.02,42.19 69.84,42.19 v1(66.95,45.08)
P2_1: length 45.2
  TOP w0.15: R31.2 R30.2 v1(99.96,40.4)
  TOP w0.178: U1.19 66.53,45.58 v1(65.94,44.98)
  L03_SIG1 w0.157: v1(65.94,44.98) 66.37,44.55 66.88,44.55 69.62,41.81 75.08,41.81 75.77,41.12 77.85,41.12 78.41,41.68 79.38,41.68 84.24,46.53 93.83,46.53 v1(99.96,40.4)
P3_0: length 45.5
  TOP w0.178: J4.8 85.12,57.3 82.07,57.3 81.56,57.81 81.56,61.49 81.28,61.77 J5.24 ; U1.23 65.14,49.9 v1(65.56,50.32)
  L03_SIG1 w0.157: v1(65.56,50.32) 68.88,50.32 76.48,57.91 76.48,59.71 79.02,62.26 85.5,62.26 86.87,60.88 J4.8
P3_1: length 144.9
  TOP w0.178: v1(65.56,51.33) 65.56,51.08 64.64,50.16 U1.24
  L03_SIG1 w0.157: v1(65.56,51.33) 65.18,51.33 64.41,50.57 63.45,50.57 63.14,50.88 62.46,50.88 58.57,54.76 v1(58.19,54.76) 55.65,57.3 30.48,57.3 30.1,57.68 20.09,57.68 13.34,64.44 J6.4
  L04_SIG2 w0.157: J18.4 13.34,17.7 10.82,20.22 10.82,30.25 20.98,40.41 20.98,49.05 17.17,52.86 17.17,56.29 13.34,60.12 J6.4 ; J5.28 74.32,62.89 61.24,62.89 58.19,59.84 v1(58.19,54.76)
P3_VDD: length 16.3
  L03_SIG1 w0.381: J17.1 118.65,21.95 ; J17.1 117.68,20.98 ; J17.1 117.68,22.91
  L03_SIG1 w1.016: 116.41,21.95 J17.1
  L04_SIG2 w0.381: 117.68,20.98 J17.1 ; J17.1 117.68,22.91 ; J17.1 118.65,21.95 ; J17.1 116.71,21.95
  BOTTOM w0.381: 73.77,48.02 R55.2 73.05,48.69 ; 61.7,29.37 FB2.1 60.99,28.71 ; 63.76,38.76 R69.2 64.43,38.04 ; v1(70.26,34.95) 70.37,34.84 R78.2 ; 73.39,37.76 FB1.1 72.67,37.09 ; 75.36,32.42 R157.2
  BOTTOM w0.635: R157.2 74.36,33.08 v1(74.3,33.15)
  vias: v1(61.11,28.45) v1(61.75,28.45) v1(63.91,37.74) v1(64.67,37.74) v1(72.92,49.05) v1(73.43,36.98) v1(73.56,49.05) v1(73.94,37.49) v1(74.42,32.51)
P4_4: length 22.6
  TOP w0.178: R23.2 v1(76.96,52.2) ; U1.31 61.14,45.85 v1(61.01,45.72)
  L03_SIG1 w0.157: v1(61.01,45.72) 61.26,45.97 61.26,47.17 62.26,48.16 62.43,48.16 62.43,48.16 68.76,48.16 70.43,49.83 74.6,49.83 v1(76.96,52.2)
P4_4_EXP: length 18
  TOP w0.178: R23.1 76.96,55.3 76.48,55.78 76.48,59.97 75.84,60.6 70.21,60.6 J5.36
P4_5: length 122.8
  TOP w0.178: J5.37 63.5,67.18 62.26,65.94 62.26,61.37 61.24,60.35 61.24,57.68 v1(60.48,56.92) ; v1(60.86,49.3) 60.64,49.08 U1.32
  L03_SIG1 w0.157: J8.8 22.2,53.11 39.27,53.11 40.16,54 48.34,54 51.79,50.55 57.99,50.55 59.69,48.84 60.4,48.84 v1(60.86,49.3)
  BOTTOM w0.178: J8.8 21.13,54.36 26.31,49.17 26.31,14.5 20.95,9.14 J21.8 ; v1(60.48,56.92) 59.05,56.92 56.92,54.79 56.92,50.98 58.09,49.81 60.35,49.81 v1(60.86,49.3)
P5_0: length 125
  TOP w0.178: U1.35 59.14,46.95 59.26,46.84 v1(59.26,46.28)
  L03_SIG1 w0.157: v1(59.26,46.28) 60.01,46.28 60.48,46.75 60.48,47.5 62.03,49.05 68.66,49.05 70.69,51.08 v1(71.65,51.08)
  L03_SIG1 w0.178: v1(59.26,46.28) 58.55,45.57 55.5,45.57 54.25,46.81 v1(53.19,46.81)
  L04_SIG2 w0.157: v1(71.65,51.08) 89.03,51.08 89.46,51.51 98.07,51.51 104.29,45.29 104.29,21.87 108.48,17.68 108.48,9.8 107.47,8.79 106.45,8.79 104.14,6.48 J24.36
  L04_SIG2 w0.178: v1(53.19,46.81) 51.68,48.32 51.68,52.44 52.6,53.37 52.6,57.53 52.52,57.62 52.52,62.17 54.83,64.48 v1(55.72,64.48)
  BOTTOM w0.178: R160.2 v1(55.72,64.48)
P5_2: length 67.5
  BOTTOM w0.178: J24.35 102.9,3.78 102.9,6.25 101.24,7.9 57.81,7.9 54.25,11.46 48.29,11.46 44.35,15.39 R136.2
P5_3: length 63.5
  BOTTOM w0.178: R148.2 44.35,12.34 45.92,10.77 54.18,10.77 57.38,7.57 98.65,7.57 100.36,5.87 100.36,3.78 J24.33
P5LP1_2: length 29.2
  TOP w0.178: v1(109.42,31.52) 109.54,31.4 SW3.1 SW3.2 ; U2.13 89.89,32.97 90.37,32.49 v1(90.37,30.28)
  L03_SIG1 w0.157: v1(109.42,31.52) 98.91,31.52 97.36,29.97 90.68,29.97 v1(90.37,30.28)
P5LP1_4: length 32.3
  TOP w0.157: U2.15 90.69,33.06 90.96,32.79 90.96,30.23 v1(91.69,29.49)
  L03_SIG1 w0.157: v1(115.63,25.97) 110.91,30.68 98.76,30.68 97.56,29.49 v1(91.69,29.49)
  BOTTOM w0.178: R106.2 v1(115.63,25.97)
P5LP_SIO_VREF: length 2.9
  TOP w0.191: v1(85.98,42.98) 86.29,42.67 U2.48
  BOTTOM w0.381: v1(85.98,42.98) R61.2 R62.2
P5LP_SWCLK: length 32.4
  TOP w0.157: U2.12 89.49,32.15 v1(89.81,31.83)
  TOP w0.178: v1(98.02,31.47) 105.26,31.47 112.8,39.01 112.8,39.65 J25.4
  L03_SIG1 w0.157: v1(98.02,31.47) 96.72,31.47 96.22,30.96 91.58,30.96 90.71,31.83 v1(89.81,31.83)
P5LP_SWDIO: length 32.9
  TOP w0.157: v1(88.54,31.65) 89.09,32.19 U2.11
  TOP w0.178: v1(97,30.71) 97.03,30.68 105.74,30.68 113.06,38 113.69,38 114.68,38.99
  L03_SIG1 w0.157: v1(88.54,31.65) 89.05,31.14 90.47,31.14 91.21,30.4 96.7,30.4 v1(97,30.71)
P5LP_VCCD: length 19.2
  TOP w0.191: U2.57 83.57,39.27 ; U2.26 93.34,38.07
  TOP w0.381: 83.57,39.27 83.54,39.24 C15.1 v1(82.14,39.95) ; 93.34,38.07 C17.1 v1(93.12,39.01)
  L03_SIG1 w0.635: v1(93.12,39.01) 92.48,39.65 92.48,40.03 91.26,41.25 83.44,41.25 v1(82.14,39.95)
P5LP_VDD: length 36.1
  TOP w0.191: U2.67 83.76,35.27 83.54,35.05 ; 83.58,41.44 83.75,41.27 U2.52 ; U2.35 91.49,42.88 ; U2.44 87.89,42.85 ; U2.59 83.63,38.47 83.54,38.38 ; U2.17 91.49,33.3 91.57,33.22 ; U2.24 93.16,37.27
  TOP w0.381: 91.57,33.22 91.87,32.92 C28.1 v1(91.87,31.45) ; 83.54,35.05 C23.1 v1(82.14,35.91) ; 87.89,42.85 87.76,42.98 C4.1 87.14,43.97 v1(86.77,44.35) ; 83.58,41.44 82.98,42.04 C8.1 v1(82.14,42.85) ; 93.16,37.27 93.35,37.47 C21.1 94.29,37.49 94.26,37.51 94.26,38.18 v1(94.39,38.3) ; 91.49,42.88 91.57,42.96 C6.1 92.35,43.97 v1(92.48,43.84) ; v1(82.14,37.16) C20.1 83.13,37.97 83.54,38.38
  L05_PWR w0.381: 114.68,48.18 J25.1 ; J25.1 113.71,49.15 ; J25.1 114.68,50.12 ; J25.1 115.65,49.15
  BOTTOM w0.381: R108.1 v1(98.11,25.08) ; R108.1 v1(97.21,26.06) ; R108.1 98.11,26.78 ; v1(92.48,43.84) 92.35,43.97 C6.1 ; C56.1 94.26,38.18 v1(94.39,38.3) ; v1(96.79,33.34) 96.32,33.81 R79.1 ; C23.1 v1(82.14,35.91) ; C20.1 v1(82.14,37.16) ; v1(86.77,44.35) 87.14,43.97 C4.1 ; C8.1 v1(82.14,42.85) ; C28.1 v1(91.87,31.45)
P5LP_XRES: length 33.6
  TOP w0.157: v1(88.42,33.17) 88.69,33.44 U2.10
  TOP w0.178: v1(97.16,32.23) 104.27,32.23 111.53,39.5 111.53,40.92 J25.3
  L03_SIG1 w0.157: v1(88.42,33.17) 90.83,33.17 91.97,32.03 93.95,32.03 94.16,32.23 v1(97.16,32.23)
P7_4: length 17.5
  TOP w0.15: U1.48 54.66,42.55 53.29,42.55 52.48,43.36 52.48,47.32 54.43,49.28 54.43,50.34 55.73,51.64 59.08,51.64 v1(59.8,52.36)
  BOTTOM w0.15: R159.2 59.83,52.34 v1(59.8,52.36)
P7_6: length 100.3
  TOP w0.178: J5.22 83.82,62.87 82.8,61.85 J3.1 ; U1.51 57.02,41.08 v1(57.05,41.05)
  L03_SIG1 w0.157: v1(46.38,41.68) 47.12,40.94 49.73,40.94 49.91,41.12 50.34,41.12 51.69,39.78 55.78,39.78 v1(57.05,41.05)
  L04_SIG2 w0.157: v1(46.38,41.68) 46.38,16.54 39.53,9.69 v1(36.46,9.69) ; v1(57.05,41.05) 55.37,42.72 55.37,48.27 59.33,52.23 59.33,52.55 59.89,53.11 61.94,53.11 v1(65.81,56.98)
  BOTTOM w0.178: J3.1 82.8,57.78 82,56.98 v1(65.81,56.98) ; R151.1 v1(36.46,9.69)
P7_7: length 93.3
  TOP w0.178: U1.52 52.77,40.58 v1(52.6,40.41) ; J12.2 13.11,49.81 41.05,49.81 v1(42.65,48.21)
  L03_SIG1 w0.157: v1(52.6,40.41) 52.6,41.3 49.94,43.97 46.89,43.97 v1(42.65,48.21)
  L04_SIG2 w0.157: v1(52.6,40.41) 51.64,39.45 51.64,27.33 50.75,26.44 50.75,21.79 61.87,10.67 62.66,10.67 63.87,9.46 63.87,7.73 63.5,7.37 J24.4
P8_4: length 78.8
  TOP w0.178: v1(63.78,36.65) 63.78,36.6 63.64,36.46 U1.75
  L04_SIG2 w0.157: v1(30.89,51.46) 37.19,51.46 39.7,48.95 47.42,48.95 50.44,45.92 50.44,41.81 51.08,41.17 52.55,41.17 57.32,36.4 63.53,36.4 v1(63.78,36.65) 64.74,36.65 65.3,36.09 65.3,34.57 67.21,32.66 67.21,24.92 66.95,24.66 66.95,14.1 66.04,13.18 J24.6
  BOTTOM w0.178: R46.2 30.77,51.58 v1(30.89,51.46)
P8_5: length 81.7
  TOP w0.178: U1.76 64.14,36.2 v1(65.18,37.24)
  L04_SIG2 w0.157: v1(31.01,55.4) 36.17,55.4 42.29,49.28 47.78,49.28 50.93,46.13 50.93,43.23 56.64,37.52 63.4,37.52 63.68,37.24 v1(65.18,37.24) 65.16,37.22 65.68,36.7 65.68,34.7 67.59,32.79 67.59,25.04 68.28,24.36 68.28,16.21 67.41,15.34 67.41,6.25 J24.8
  BOTTOM w0.178: R45.2 30.8,55.61 v1(31.01,55.4)
P9_4: length 229.5
  TOP w0.178: U1.4 68.91,38.08 69.24,37.74 69.24,36.93 70.33,35.84 71.27,35.84 72.67,34.44 v1(72.67,33.68)
  L03_SIG1 w0.157: 27.64,17.17 17.81,17.17 J18.5 ; v1(72.01,18.03) 65.79,24.26 58.22,24.26 57.05,25.43 46.69,25.43
  L03_SIG1 w0.178: 27.64,17.17 35.89,25.43 46.69,25.43
  L04_SIG2 w0.157: J18.5 15.88,18.06 13.19,20.74 13.19,30.21 23.52,40.54 23.52,48.92 19.71,52.73 19.71,56.29 15.88,60.12 J6.5 ; J5.11 95.17,65.96 93.4,65.96 92.83,65.4 92.83,63.27 90.58,61.01 89.51,61.01 88.16,59.66 88.16,58.32 87,57.15 72.64,57.15 68.1,52.6 68.1,49.56 65.94,47.4 65.94,46.38 66.75,45.57 67.26,45.57 68.1,44.73 68.1,39.14 69.24,38 69.24,37.11 v1(72.67,33.68) 72.67,33.6 75.01,31.27 82.85,31.27 84.05,30.07 88.14,30.07 88.37,29.85 88.37,27.56 85.47,24.66 83.95,24.66 78.69,19.41 73.48,19.41 72.11,18.03 v1(72.01,18.03)
  BOTTOM w0.178: v1(72.67,33.68) 72.6,33.62 72.2,33.62 71.92,33.9 R76.2
P9_5: length 136.4
  TOP w0.178: v1(66.7,25.3) 73.15,31.75 73.15,34.98 71.65,36.47 v1(70.89,36.47) 70.64,36.47 69.62,37.49 69.62,38 69.04,38.58 U1.5
  L03_SIG1 w0.157: 12.06,23.37 16.92,28.22 42.44,28.22 44.7,25.96 56.74,25.96 56.9,25.81 59.94,25.81 60.38,25.37 66.62,25.37 v1(66.7,25.3)
  L04_SIG2 w0.157: v1(70.89,36.47) 70.38,36.47 69.62,37.24 69.62,38.13 68.48,39.27 68.48,45.01 67.44,46.05 66.78,46.05 66.32,46.51 66.32,47.14 68.48,49.3 68.48,52.1 73.13,56.74 89.24,56.74 90.7,58.21 90.7,59.84 93.83,62.97 96.75,62.97 97.82,64.03 97.82,66.07 J5.9
  BOTTOM w0.178: R73.2 71.27,36.09 v1(70.89,36.47)
PERI_HRPWM_0: length 36.2
  TOP w0.15: v1(57.68,53.54) 53.92,53.54 52.73,52.35 52.73,51.59 49.2,48.06 v1(47.4,48.06)
  TOP w0.178: R32.2 v1(33.95,35.98)
  L04_SIG2 w0.157: v1(47.4,48.06) 47.02,47.68 46.18,47.68 41.68,43.18 41.68,41.15 36.51,35.98 v1(33.95,35.98)
  BOTTOM w0.15: R159.1 58.33,52.9 v1(57.68,53.54)
PERI_HRPWM_0_EXP: length 94
  TOP w0.178: R34.1 v1(36.58,36.96)
  BOTTOM w0.178: v1(36.58,36.96) 39.78,40.16 39.78,56.79 43.59,60.6 51.89,60.6 52.81,59.69 56.77,59.69 57.68,60.6 104.04,60.6 106.68,63.25 J5.4
PERI_HRPWM_1: length 37.8
  TOP w0.178: R4.2 32.66,54 31.9,53.24 31.9,51.71 33.4,50.22 39.07,50.22 41.38,52.53 v1(51.18,52.53) ; v1(53.49,41.43) 53.64,41.58 U1.50
  L04_SIG2 w0.157: v1(51.18,52.53) 51.36,52.35 51.36,43.56 v1(53.49,41.43)
PERI_HRPWM_1_EXP: length 79.7
  TOP w0.178: R8.1 v1(32.66,52.5)
  BOTTOM w0.178: v1(32.66,52.5) 41.15,60.99 52.04,60.99 53.01,60.02 56.62,60.02 57.58,60.99 102.64,60.99 104.14,62.48 J5.6
PERI_HRPWM_2: length 52.9
  TOP w0.178: v1(59.87,46.86) 59.94,46.86 60.14,47.06 U1.33
  L03_SIG1 w0.157: v1(59.87,46.86) 59.87,47.45 61.9,49.48 68.59,49.48 72.34,53.24 v1(72.54,53.24)
  L04_SIG2 w0.157: v1(72.54,53.24) 73.94,54.64 80.62,54.64 81.31,55.32 95.71,55.32 98.32,57.94 98.32,60.22 101.6,63.5 J5.8
PERI_HRPWM_3: length 49.1
  TOP w0.178: v1(60.1,49.3) 59.64,48.85 U1.34
  L03_SIG1 w0.157: v1(70.7,53.3) 68.22,50.83 65.3,50.83 64.31,49.83 60.63,49.83 v1(60.1,49.3)
  L04_SIG2 w0.157: v1(70.7,53.3) 71.53,54.13 71.53,54.51 73.41,56.39 91.82,56.39 93.24,57.81 93.24,60.1 95.15,62 97.43,62 99.06,63.63 J5.10
POT: length 120.2
  TOP w0.157: v1(43.84,28.07) 43.99,28.22 43.99,46.38 46.08,48.46 v1(46.89,48.46)
  TOP w0.178: v1(115.27,54.32) R2.2
  L03_SIG1 w0.178: v1(43.84,28.07) 44.37,27.53 48.97,27.53 49.42,27.98 51.55,27.98 52.45,28.88 57.91,28.88 58.12,29.08 61.06,29.08 61.21,28.93 62.33,28.93 62.87,28.4 v1(62.89,28.4)
  BOTTOM w0.178: v1(115.27,54.32) 109.84,54.32 107.75,56.41 64.49,56.41 63.19,57.72 58.35,57.72 55.96,55.32 50.62,55.32 47.65,52.35 47.65,49.23 v1(46.89,48.46) ; R90.2 v1(62.89,28.4)
POT_EXP: length 79
  TOP w0.178: v1(115.72,24.79) 116.1,25.17 116.1,51.08 116.68,51.65 R3.1
  L04_SIG2 w0.157: J24.21 87.73,1.17 110.64,1.17 112.8,3.33 112.8,12.6 114.33,14.12 114.33,23.39 v1(115.72,24.79)
PWM_SHIELD: length 179.2
  TOP w0.178: U1.36 v1(58.64,46.82)
  L03_SIG1 w0.157: J8.9 23.42,54.36 22.12,55.65 20.35,55.65 19.71,55.02 19.71,53.49 21.23,51.97 38.86,51.97 41.35,49.48 51.87,49.48 52.17,49.17 55.96,49.17 56.77,48.36 57.48,48.36 58.64,47.2 v1(58.64,46.82)
  BOTTOM w0.178: J24.12 72.49,3.91 58.37,3.91 53.37,8.92 38.76,8.92 36.73,6.88 27.84,6.88 26.04,5.08 J21.9 23.5,10.16 27.08,13.74 27.08,50.77 J8.9 22.07,55.78 20.22,55.78 19.71,55.27 19.71,52.86 16.36,49.5 8.64,49.5 6.99,47.85 J12.1
SPI_CLK_ARD: length 155.7
  TOP w0.178: J3.6 64.97,53.92 63.75,53.92 62.66,52.83 62.66,52.2 v1(62.61,52.15) ; U1.44 v1(56.01,44.58)
  L03_SIG1 w0.157: J6.6 24.56,58.37 44.75,58.37 44.78,58.39 44.81,58.39 44.83,58.42 55.32,58.42 58.39,55.35 59.77,55.35 62.61,52.5 v1(62.61,52.15) ; J3.6 71.6,57.56 73.43,57.56 73.94,58.06 73.94,60.22 77.09,63.37 87.5,63.37 J5.18
  L04_SIG2 w0.157: v1(62.61,52.15) 60.83,52.15 56.44,47.75 56.44,45.57 56.01,45.13 v1(56.01,44.58) ; J18.6 18.41,18.08 14.61,21.89 14.61,23.36 J16.4 26.44,35.2 26.44,50.57 26,51.02 26,54.7 18.41,62.28 J6.6
SPI_CLK_FLASH: length 4.3
  TOP w0.15: U3.6 74.7,27.89 v1(74.57,27.76)
  BOTTOM w0.15: v1(74.57,27.76) 74.8,27.99 75.79,27.99 75.95,27.84 R101.2
SPI_CLK_MCU: length 34.4
  TOP w0.178: v1(63.12,35.76) 63.14,35.74 U1.74
  L03_SIG1 w0.157: v1(63.12,35.76) 63.12,35.03 63.45,34.7 68,34.7 72.19,30.51 75.46,30.51 77.14,28.83 79.78,28.83 79.94,28.67 79.94,27.95 80.1,27.79 80.41,27.79 80.57,27.95 80.57,28.67 80.73,28.83 82.88,28.83 83.03,28.67 83.03,27.08 82.78,26.82 78.03,26.82 v1(77.62,27.23)
  BOTTOM w0.15: v1(77.62,27.23) 77.45,27.05 R100.2
SPI_CS01_ARD: length 50.3
  TOP w0.178: v1(57.45,43.64) 56.89,43.08 U1.47
  L03_SIG1 w0.157: v1(57.45,43.64) 58.01,43.64 60.86,46.48 60.86,47.32 62.2,48.67 68.78,48.67 70.69,50.57 72.52,50.57 74.09,52.15 74.09,53.62 77.72,57.25 J3.3
  L04_SIG2 w0.157: J3.3 78.84,57.94 83.97,57.94 85.12,59.08 85.12,59.84 87.25,61.98 89.92,61.98 91.44,63.5 J5.16
SPI_CS_FLASH: length 4.1
  TOP w0.15: v1(84.43,25.43) 84.35,25.35 U3.1
  BOTTOM w0.15: R114.2 83.9,24.87 84.05,24.72 84.28,24.72 84.43,24.87 v1(84.43,25.43)
SPI_MISO_ARD: length 160.7
  TOP w0.178: v1(62.71,51.38) 63.22,51.89 63.22,52.58 64.01,53.37 66.95,53.37 J3.5 ; U1.46 v1(56.15,43.58)
  L03_SIG1 w0.157: J3.5 72.64,60.33 74.96,62.64 74.96,65.53 75.51,66.09 85.04,66.09 J5.20 ; v1(62.71,51.38) 63.17,51.84 63.17,52.78 60.05,55.91 58.62,55.91 55.55,58.98 29.03,58.98 J6.8
  L04_SIG2 w0.157: J18.8 22.05,13.79 20.24,13.79 19.74,14.3 19.74,18.67 17.14,21.26 J16.5 27.33,33.55 27.33,54.64 19.71,62.26 19.71,65.43 20.22,65.94 22.07,65.94 J6.8 ; v1(56.15,43.58) 56.57,43.99 56.57,44.65 58.12,46.2 58.12,48.08 61.37,51.33 62.66,51.33 v1(62.71,51.38)
SPI_MISO_FLASH: length 4.2
  TOP w0.15: v1(84.3,27.2) 84.3,26.95 83.97,26.62 U3.2
  BOTTOM w0.15: R105.2 83.9,27.61 v1(84.3,27.2)
SPI_MOSI_ARD: length 157.3
  TOP w0.178: v1(57.81,44.63) 57.2,44.63 56.65,44.08 U1.45 ; J3.4 68.99,52.86 64.11,52.86 63.75,52.5 63.75,51.49 v1(64.16,51.08)
  L03_SIG1 w0.157: J6.7 22.4,65.96 24.13,65.96 30.63,59.46 55.65,59.46 58.7,56.41 60.25,56.41 63.68,52.98 63.68,51.56 v1(64.16,51.08)
  L03_SIG1 w0.178: J3.4 75.18,60.25 77.6,62.66 91.87,62.66 J5.14
  L04_SIG2 w0.157: v1(64.16,51.08) 64.16,50.19 58.57,44.6 57.84,44.6 v1(57.81,44.63) ; J6.7 27.76,57.71 27.76,31.45 J16.6 19.68,20.24 20.95,18.97 J18.7
SPI_MOSI_FLASH: length 4.1
  TOP w0.15: v1(74.96,29.87) 74.29,29.87 74.14,29.72 74.14,29.31 74.29,29.16 U3.5
  BOTTOM w0.15: v1(74.96,29.87) 74.96,29.82 75.16,29.62 R96.2
TCLK_SWCLK: length 35.8
  TOP w0.15: v1(120.56,45.48) 120.68,45.59 J11.4
  TOP w0.178: R38.1 104.01,37.36 104.72,38.07 104.72,38.91 105.66,39.85 107.04,39.85 J14.4
  L03_SIG1 w0.165: v1(120.56,45.48) 118.77,43.69 118.77,39.4 115.85,36.47 105.69,36.47 104.6,37.57 104.6,38.94 105.54,39.88 J14.4
  BOTTOM w0.15: v1(120.56,45.48) 120.17,45.87 R59.1
TCLK_SWCLK_MCU: length 47.5
  TOP w0.15: R38.2 R37.2 99.96,38.26 v1(99.94,38.29)
  TOP w0.178: v1(66.7,43.97) 66.81,44.08 U1.16
  L03_SIG1 w0.157: v1(66.7,43.97) 69.42,41.25 73.81,41.25 76.86,38.2 80.09,38.2 80.87,38.99 80.87,40.36 85.42,44.91 85.42,45.34 85.83,45.75 87.35,45.75 88.32,44.78 91.57,44.78 91.87,44.48 95.13,44.48 99.16,40.44 99.16,39.07 v1(99.94,38.29)
TCPWM1_COMPL_EXP: length 42
  TOP w0.178: v1(83.68,54.52) 83.6,54.6 R15.1 ; J4.6 88.77,55.88 80.06,55.88 78.83,57.11 78.83,60.03 77.62,61.24 70.89,61.24 68.58,63.55 J5.34
  L03_SIG1 w0.157: J4.6 88.32,55.42 84.51,55.42 83.68,54.6 v1(83.68,54.52)
TCPWM1_COMPL_EXP_MCU: length 30.9
  TOP w0.178: v1(62.69,46) 62.64,46.04 U1.28 ; R15.2 v1(82.68,52.2)
  L03_SIG1 w0.157: v1(82.68,52.2) 81.27,50.79 81.27,46.73 78.18,43.64 70.59,43.64 67.92,46.3 66.55,46.3 65.96,46.89 63.09,46.89 62.69,46.48 v1(62.69,46)
TCPWM1_EXP: length 54
  TOP w0.178: v1(85.6,54.52) 85.52,54.6 R19.1
  L03_SIG1 w0.157: v1(85.6,54.52) 92.49,54.52 J4.4 95.28,60.81 95.28,68.05 94.84,68.48 67.21,68.48 J5.35
TCPWM1_EXP_MCU: length 32.2
  TOP w0.178: v1(86.16,52.53) 85.59,53.1 R19.2 ; U1.27 63.14,46.76 v1(63.55,46.35)
  L03_SIG1 w0.157: v1(86.16,52.53) 86.16,51.08 78.38,43.31 70.33,43.31 67.69,45.95 66.32,45.95 65.91,46.35 v1(63.55,46.35)
TCPWM2_COMPL_EXP_MCU: length 39.6
  TOP w0.178: U1.3 66.28,37.58 v1(64.67,35.97)
  L04_SIG2 w0.157: v1(64.67,35.97) 64.67,34.57 65.43,33.81 65.43,31.7 66.17,30.96 66.17,24.94 66.57,24.54 66.57,14.5 65.56,13.49 65.56,8.28 64.8,7.52 64.8,3.84 J24.3
TCPWM2_EXP_MCU: length 60.1
  TOP w0.178: U1.1 67.06,36.58 v1(66.83,36.35)
  L04_SIG2 w0.157: v1(66.83,36.35) 64.54,38.63 59.08,38.63 58.75,38.96 58.75,39.85 58.26,40.35 56.76,40.35 54.66,42.45 54.66,48.59 58.7,52.63 58.7,59.56 61.59,62.46 76.43,62.46 77.5,63.53 77.5,66.07 J5.25
TCPWM_518: length 60
  TOP w0.178: R28.1 v1(98.46,40.28)
  L04_SIG2 w0.157: v1(98.46,40.28) 99.39,39.36 99.39,35.56 102.11,32.84 102.11,26.31 100.86,25.07 100.86,10.01 98.68,7.82 78.94,7.82 J24.14
TCPWM_518_COMPL: length 62
  TOP w0.178: R30.1 98.46,38.75 v1(98.83,38.38)
  L04_SIG2 w0.157: J24.11 74.96,3.84 74.96,6.12 77.04,8.2 97.74,8.2 98.32,8.79 98.32,17.17 99.54,18.39 99.54,24.28 101.73,26.47 101.73,32.44 99.06,35.1 99.06,38.15 v1(98.83,38.38)
TCPWM_COMPL_EXP: length 17.3
  TOP w0.178: R9.1 v1(78.87,55.47) ; J3.2 80.26,60.38 77.88,62.76 73.13,62.76 J5.32
  L03_SIG1 w0.157: J3.2 80.26,56.87 v1(78.87,55.47)
TCPWM_COMPL_EXP_MCU: length 24.9
  TOP w0.178: R9.2 v1(78.87,52.2) ; v1(61.64,45.36) U1.30
  L03_SIG1 w0.157: v1(61.64,45.36) 61.67,45.39 61.67,47.04 62.47,47.84 75.04,47.84 78.87,51.66 v1(78.87,52.2)
TCPWM_EXP: length 40.4
  TOP w0.178: v1(81.79,54.52) 81.71,54.6 R11.1 ; J4.7 89.41,57.78 88.14,56.52 80.54,56.52 79.16,57.9 79.16,60.46 77.62,62 71.78,62 69.88,63.91 69.88,65.94 68.58,67.23 J5.33
  L03_SIG1 w0.157: v1(81.79,54.52) 81.79,54.6 83.37,56.18 86.54,56.18 J4.7
TCPWM_EXP_MCU: length 23
  TOP w0.178: R11.2 v1(80.77,52.2) ; U1.29 v1(62.14,46.77)
  L03_SIG1 w0.157: v1(80.77,52.2) 80.14,52.2 75.47,47.53 62.9,47.53 v1(62.14,46.77)
TDI: length 33.7
  TOP w0.15: J11.8 v1(120.42,48.13)
  TOP w0.178: R29.1 103.99,41.3 105.11,42.42 J14.8
  L03_SIG1 w0.165: J14.8 105.89,42.42 105.08,43.23 105.08,49.96 106.15,51.03 117.53,51.03 v1(120.42,48.13)
  BOTTOM w0.15: R52.1 120.4,48.16 v1(120.42,48.13)
TDO: length 37.7
  TOP w0.15: J11.6 v1(120.68,46.86)
  TOP w0.178: R31.1 103.91,39.4 105.66,41.15 J14.6
  L03_SIG1 w0.165: J14.6 105.71,41.15 104.57,42.29 104.57,50.14 106.27,51.84 117.5,51.84 120.98,48.36 120.98,47.17 v1(120.68,46.86)
TMS_SWDIO: length 34.4
  TOP w0.15: v1(120.68,44.48) 120.83,44.32 J11.2
  TOP w0.178: J14.2 105.89,38.61 105.51,38.23 105.51,37.03 103.81,35.33 R40.1
  L03_SIG1 w0.165: J14.2 105.92,38.61 105.69,38.38 105.69,37.87 106.22,37.34 114.94,37.34 118.01,40.41 118.01,44.12 119.99,46.1 120.73,46.1 121.11,45.72 121.11,44.91 v1(120.68,44.48)
  BOTTOM w0.15: v1(120.68,44.48) 120.64,44.48 120.39,44.22 R60.1
TMS_SWDIO_MCU: length 50.2
  TOP w0.15: v1(99.94,36.35) 99.96,36.32 R39.2 R40.2
  TOP w0.178: v1(66.07,44.09) 66.55,44.58 U1.17
  L03_SIG1 w0.157: v1(66.07,44.09) 66.07,43.69 69.05,40.71 73.39,40.71 76.45,37.64 80.31,37.64 81.51,38.84 81.51,40.11 86.23,44.83 87.48,44.83 88.09,44.22 91.14,44.22 92.53,42.82 95.96,42.82 97.87,40.92 97.87,38.42 v1(99.94,36.35)
UART_1_RX: length 52.9
  TOP w0.157: U2.21 92.86,36.07 94.01,34.93 v1(94.01,34.75)
  L03_SIG1 w0.157: v1(94.01,34.75) 94.01,33.5 93.32,32.82 92.61,32.82 91.36,34.06 84.79,34.06 84.07,34.77 80.24,34.77 78.41,36.6 76.23,36.6 74.27,38.56 71.7,38.56 70.36,37.21 67.59,37.21 66.34,38.46 57.86,38.46 57.3,39.01 57.3,40.28 57.56,40.54 57.56,41.3 57.3,41.55 55.02,41.55 v1(53.37,43.21)
  BOTTOM w0.178: R63.1 53.15,42.99 v1(53.37,43.21)
UART_1_RX_EXP: length 55.6
  TOP w0.178: J24.7 68.38,2.54 67.34,3.58 67.34,5.99 63.27,10.06 v1(62.56,10.06)
  L04_SIG2 w0.157: v1(47.6,47.45) 48.41,46.63 48.41,42.9 49.3,42.01 49.3,22.63 61.87,10.06 v1(62.56,10.06)
  BOTTOM w0.178: R58.1 47.94,47.79 v1(47.6,47.45)
UART_1_TX: length 54.6
  TOP w0.157: U2.20 92.75,35.67 93.37,35.05 v1(93.37,33.81)
  L03_SIG1 w0.157: v1(93.37,33.81) 92.76,34.42 85.19,34.42 84.45,35.15 80.59,35.15 78.64,37.11 76.35,37.11 74.4,39.07 70.05,39.07 69.6,38.61 67.36,38.61 67.08,38.89 58.12,38.89 57.63,39.37 57.63,39.98 57.94,40.28 57.94,41.43 57.43,41.94 55.65,41.94 53.87,43.71 53.34,43.71 52.6,44.45 52.6,47.04 53.09,47.52 v1(53.37,47.52)
  BOTTOM w0.178: v1(53.37,47.52) 53.1,47.79 R56.1
UART_1_TX_EXP: length 51.3
  TOP w0.178: v1(63.07,9.58) 64.8,7.85 64.8,3.84 66.04,2.59 J24.5
  L04_SIG2 w0.157: v1(47.56,42.99) 47.27,42.7 47.27,22.05 52.17,17.15 54.15,17.15 61.75,9.55 63.04,9.55 v1(63.07,9.58)
  BOTTOM w0.178: R65.1 v1(47.56,42.99)
UART_CTS_1: length 111.8
  TOP w0.178: U1.39 57.14,49.21 v1(57.05,49.3) ; v1(97.99,50.77) 94.49,54.28 J4.5
  L04_SIG2 w0.157: v1(72.54,54.64) 73.94,56.03 92.74,56.03 94.49,57.78 J4.5 ; J24.29 97.82,3.84 97.82,5.79 98.4,6.38 102.39,6.38 105.94,9.93 105.94,18.72 103.76,20.9 103.76,45 v1(97.99,50.77)
  BOTTOM w0.178: v1(72.54,54.64) 70.87,54.64 64.67,48.44 57.91,48.44 v1(57.05,49.3)
UART_RTS_1: length 141.4
  TOP w0.178: U1.41 v1(55.98,46.08)
  L04_SIG2 w0.157: J24.31 100.36,3.84 104.93,3.84 105.44,4.34 105.44,6.38 106.91,7.85 109.19,7.85 110.95,9.6 110.95,16.23 104.8,22.38 104.8,45.36 98.2,51.97 89.23,51.97 88.77,51.51 72.87,51.51 v1(72.29,52.1) 74.47,54.28 80.77,54.28 81.48,54.99 96.9,54.99 99.57,57.66 J4.3
  BOTTOM w0.178: v1(72.29,52.1) 69.62,52.1 65.02,47.5 56.9,47.5 55.98,46.58 v1(55.98,46.08)
UART_RX: length 12.4
  TOP w0.178: U1.42 53.79,45.58 v1(53.24,46.13)
  BOTTOM w0.178: J10.2 46.3,50.16 46.24,50.1 46.24,47.84 47.79,46.29 R58.2 R57.1 R56.2 53.07,46.29 v1(53.24,46.13)
UART_RX_0_MIK: length 182.8
  TOP w0.178: v1(65.05,51.84) 65.05,51.21 64.14,50.3 U1.25 ; v1(62.64,55.8) 62.15,55.32 55.04,55.32 49.12,49.4 45.69,49.4 43.94,47.65 42.37,47.65 40.72,49.3 15.14,49.3 12.06,46.23
  L03_SIG1 w0.157: J5.31 69.88,66.07 69.88,63.65 68.88,62.66 66.34,62.66 63.78,60.1 63.78,56.95 v1(62.64,55.8) 62.64,55.75 65.05,53.34 v1(65.05,51.84)
  L04_SIG2 w0.157: v1(75.34,53.49) 99.09,53.49 J4.1 ; J18.1 5.71,37.85 12.06,44.2 12.06,46.23 9.25,49.05 8.53,49.05 4.47,53.11 4.47,58.19 5.71,59.44 J6.1
  BOTTOM w0.157: v1(62.64,55.8) 63.01,55.43 73.4,55.43 v1(75.34,53.49)
UART_TX: length 15.2
  TOP w0.178: U1.43 53.84,45.08 v1(53.24,44.48)
  BOTTOM w0.178: v1(53.24,44.48) 53.22,44.49 R63.2 R64.1 R65.2 47.69,44.49 43.76,48.41 J10.1
UART_TX_0_MIK: length 175.3
  TOP w0.178: v1(62.76,50.32) 63.64,49.44 U1.26 ; J5.29 74.9,66.07 84.48,66.07 85.12,65.43 85.12,63.65 86.89,61.87 99.29,61.87 J4.2 ; J12.4 17.2,48.82 40.49,48.82 42.01,47.29 44.22,47.29 45.95,49.02 49.43,49.02 v1(52.15,51.74)
  L03_SIG1 w0.157: v1(52.15,51.74) 58.32,51.74 59.74,50.32 v1(62.76,50.32)
  L04_SIG2 w0.157: 8.26,64.52 8.26,59.31 7.17,58.23 7.17,52.95 9.37,50.75 10.08,50.75 J12.4 ; v1(52.15,51.74) 53.49,53.09 53.49,57.81 56.67,60.99 56.67,62.51 60.22,66.07 72.42,66.07 J5.29
  BOTTOM w0.178: J12.4 14.61,34.52 8.26,28.17 8.26,15.24
